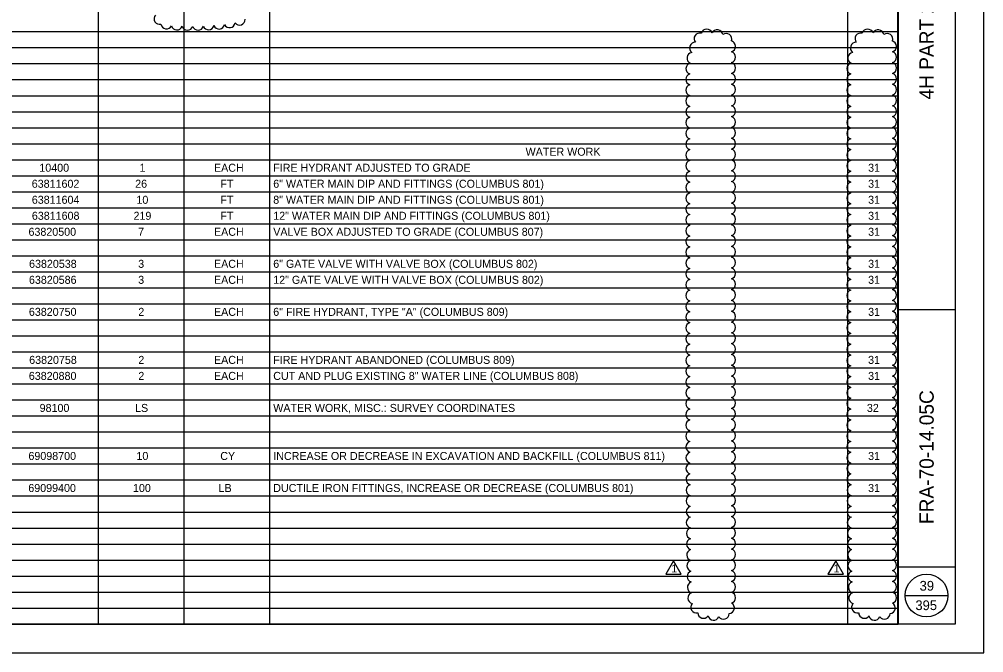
# Model space of a CAD drawing. Extents: x 0 to 34, y 0 to 22.
# Drawn here: x 17.12 to 34, y 0 to 11.08 of the extents above; entities that cross this region are included whole.
import ezdxf

# ---------------------------------------------------------------- set-up
doc = ezdxf.new("R2010")
doc.units = 0
for name, color, linetype in [('SH_Border', 7, 'Continuous'), ('SH_Cut_Line', 7, 'Continuous'), ('SH_Data', 7, 'Continuous'), ('SH_Text', 7, 'Continuous'), ('TX_P_1000', 7, 'Continuous')]:
    doc.layers.add(name, color=color, linetype=linetype)

msp = doc.modelspace()

# ---------------------------------------------------------------- linework, layer by layer
at = {"layer": 'SH_Border'}
for p, q in [((32.5, 0.5), (32.5, 21.5)), ((32.5, 6), (33.5, 6)), ((32.5, 1.5), (33.5, 1.5))]:
    msp.add_line(p, q, dxfattribs=at)
msp.add_lwpolyline([(2, 21.5), (33.5, 21.5), (33.5, 0.5), (2, 0.5)], close=True, dxfattribs=at)
at = {"layer": 'SH_Cut_Line'}
msp.add_lwpolyline([(0, 0), (34, 0), (34, 22), (0, 22)], close=True, dxfattribs=at)
at = {"layer": 'SH_Data'}
for p, q in [((18.504, 21.5), (18.504, 0.5)), ((20.002, 21.5), (20.002, 0.5)), ((21.501, 21.5), (21.501, 0.5)), ((31.614, 21.5), (31.614, 0.5)), ((32.504, 21.5), (32.504, 0.5)), ((2, 10.86), (32.504, 10.86)), ((2, 10.58), (32.504, 10.58)), ((2, 10.3), (32.504, 10.3)), ((2, 10.02), (32.504, 10.02)), ((2, 9.74), (32.504, 9.74)), ((2, 9.46), (32.504, 9.46)), ((2, 9.18), (32.504, 9.18)), ((2, 8.9), (32.504, 8.9)), ((2, 8.62), (32.504, 8.62)), ((2, 8.34), (32.504, 8.34)), ((2, 8.06), (32.504, 8.06)), ((2, 7.78), (32.504, 7.78)), ((2, 7.5), (32.504, 7.5)), ((2, 7.22), (32.504, 7.22)), ((2, 6.94), (32.504, 6.94)), ((2, 6.66), (32.504, 6.66)), ((2, 6.38), (32.504, 6.38)), ((2, 6.1), (32.504, 6.1)), ((2, 5.82), (32.504, 5.82)), ((2, 5.54), (32.504, 5.54)), ((2, 5.26), (32.504, 5.26)), ((2, 4.98), (32.504, 4.98)), ((2, 4.7), (32.504, 4.7)), ((2, 4.42), (32.504, 4.42)), ((2, 4.14), (32.504, 4.14)), ((2, 3.86), (32.504, 3.86)), ((2, 3.58), (32.504, 3.58)), ((2, 3.3), (32.504, 3.3)), ((2, 3.02), (32.504, 3.02)), ((2, 2.74), (32.504, 2.74)), ((2, 2.46), (32.504, 2.46)), ((2, 2.18), (32.504, 2.18)), ((2, 1.9), (32.504, 1.9)), ((2, 1.62), (32.504, 1.62)), ((2, 1.34), (32.504, 1.34)), ((2, 1.06), (32.504, 1.06)), ((32.625, 1), (33.375, 1)), ((2, 0.78), (32.504, 0.78)), ((2, 0.5), (32.504, 0.5))]:
    msp.add_line(p, q, dxfattribs=at)
msp.add_circle((33, 1), 0.375, dxfattribs=at)
at = {"layer": 'TX_P_1000'}
for points in [[(28.571, 1.608), (28.435, 1.372), (28.708, 1.372)], [(31.411, 1.608), (31.274, 1.372), (31.547, 1.372)]]:
    msp.add_lwpolyline(points, close=True, dxfattribs=at)
for centre, radius, start, end in [((19.578, 11.085), 0.0976, 139.2641, 284.2641), ((19.699, 11.005), 0.0976, 188.32, 333.32), ((20.62, 11.003), 0.0976, 202.8824, 347.8824), ((20.803, 11.026), 0.0976, 206.7346, 351.7346), ((20.977, 11.072), 0.0977, 217.3339, 2.3339), ((19.88, 10.986), 0.0976, 195.1082, 340.1082), ((20.065, 10.982), 0.0976, 197.1836, 342.1836), ((20.251, 10.983), 0.0976, 198.6029, 343.6029), ((20.436, 10.99), 0.0976, 200.3873, 345.3873), ((29.031, 10.736), 0.099, 74.4093, 219.4093), ((29.153, 10.805), 0.0991, 19.2496, 164.2496), ((29.336, 10.794), 0.0991, 9.041, 154.041), ((29.491, 10.729), 0.099, 340.6755, 125.6755), ((31.847, 10.736), 0.099, 74.4093, 219.4093), ((31.969, 10.805), 0.0991, 19.2496, 164.2496), ((32.152, 10.794), 0.0991, 9.041, 154.041), ((32.308, 10.729), 0.099, 340.6755, 125.6755), ((28.95, 10.574), 0.0991, 87.314, 232.314), ((29.557, 10.601), 0.0992, 288.6913, 73.6913), ((31.766, 10.574), 0.0991, 87.314, 232.314), ((32.373, 10.601), 0.0992, 288.6913, 73.6913), ((28.906, 10.398), 0.0991, 99.6335, 244.6335), ((29.559, 10.413), 0.0991, 287.5, 72.5), ((31.722, 10.398), 0.0991, 99.6335, 244.6335), ((32.375, 10.413), 0.0991, 287.5, 72.5), ((28.889, 10.213), 0.0991, 105.2456, 250.2456), ((29.559, 10.224), 0.0991, 287.5, 72.5), ((31.706, 10.213), 0.0991, 105.2456, 250.2456), ((32.375, 10.224), 0.0991, 287.5, 72.5), ((29.559, 10.035), 0.0991, 287.5, 72.5), ((32.375, 10.035), 0.0991, 287.5, 72.5), ((28.886, 10.025), 0.0991, 107.4797, 252.4797), ((31.702, 10.025), 0.0991, 107.4797, 252.4797), ((28.885, 9.836), 0.0991, 107.5, 252.5), ((29.559, 9.846), 0.0991, 287.5, 72.5), ((31.702, 9.836), 0.0991, 107.5, 252.5), ((32.375, 9.846), 0.0991, 287.5, 72.5), ((28.885, 9.647), 0.0991, 107.5, 252.5), ((29.559, 9.657), 0.0991, 287.5, 72.5), ((31.702, 9.647), 0.0991, 107.5, 252.5), ((32.375, 9.657), 0.0991, 287.5, 72.5), ((28.885, 9.458), 0.0991, 107.5, 252.5), ((29.559, 9.468), 0.0991, 287.5, 72.5), ((31.702, 9.458), 0.0991, 107.5, 252.5), ((32.375, 9.468), 0.0991, 287.5, 72.5), ((28.885, 9.269), 0.0991, 107.5, 252.5), ((29.559, 9.279), 0.0991, 287.5, 72.5), ((31.702, 9.269), 0.0991, 107.5, 252.5), ((32.375, 9.279), 0.0991, 287.5, 72.5), ((28.885, 9.08), 0.0991, 107.5, 252.5), ((29.559, 9.09), 0.0991, 287.5, 72.5), ((31.702, 9.08), 0.0991, 107.5, 252.5), ((32.375, 9.09), 0.0991, 287.5, 72.5), ((28.885, 8.891), 0.0991, 107.5, 252.5), ((29.559, 8.901), 0.0991, 287.5, 72.5), ((31.702, 8.891), 0.0991, 107.5, 252.5), ((32.375, 8.901), 0.0991, 287.5, 72.5), ((28.885, 8.702), 0.0991, 107.5, 252.5), ((29.559, 8.712), 0.0991, 287.5, 72.5), ((31.702, 8.702), 0.0991, 107.5, 252.5), ((32.375, 8.712), 0.0991, 287.5, 72.5), ((28.885, 8.513), 0.0991, 107.5, 252.5), ((29.559, 8.523), 0.0991, 287.5, 72.5), ((31.702, 8.513), 0.0991, 107.5, 252.5), ((32.375, 8.523), 0.0991, 287.5, 72.5), ((28.885, 8.324), 0.0991, 107.5, 252.5), ((29.559, 8.334), 0.0991, 287.5, 72.5), ((31.702, 8.324), 0.0991, 107.5, 252.5), ((32.375, 8.334), 0.0991, 287.5, 72.5), ((28.885, 8.135), 0.0991, 107.5, 252.5), ((29.559, 8.145), 0.0991, 287.5, 72.5), ((31.702, 8.135), 0.0991, 107.5, 252.5), ((32.375, 8.145), 0.0991, 287.5, 72.5), ((28.885, 7.946), 0.0991, 107.5, 252.5), ((29.559, 7.956), 0.0991, 287.5, 72.5), ((31.702, 7.946), 0.0991, 107.5, 252.5), ((32.375, 7.956), 0.0991, 287.5, 72.5), ((28.885, 7.757), 0.0991, 107.5, 252.5), ((29.559, 7.767), 0.0991, 287.5, 72.5), ((31.702, 7.757), 0.0991, 107.5, 252.5), ((32.375, 7.767), 0.0991, 287.5, 72.5), ((28.885, 7.568), 0.0991, 107.5, 252.5), ((29.559, 7.578), 0.0991, 287.5, 72.5), ((31.702, 7.568), 0.0991, 107.5, 252.5), ((32.375, 7.578), 0.0991, 287.5, 72.5), ((28.885, 7.379), 0.0991, 107.5, 252.5), ((29.559, 7.389), 0.0991, 287.5, 72.5), ((31.702, 7.379), 0.0991, 107.5, 252.5), ((32.375, 7.389), 0.0991, 287.5, 72.5), ((28.885, 7.19), 0.0991, 107.5, 252.5), ((29.559, 7.2), 0.0991, 287.5, 72.5), ((31.702, 7.19), 0.0991, 107.5, 252.5), ((32.375, 7.2), 0.0991, 287.5, 72.5), ((28.885, 7.001), 0.0991, 107.5, 252.5), ((29.559, 7.011), 0.0991, 287.5, 72.5), ((31.702, 7.001), 0.0991, 107.5, 252.5), ((32.375, 7.011), 0.0991, 287.5, 72.5), ((28.885, 6.812), 0.0991, 107.5, 252.5), ((29.559, 6.822), 0.0991, 287.5, 72.5), ((31.702, 6.812), 0.0991, 107.5, 252.5), ((32.375, 6.822), 0.0991, 287.5, 72.5), ((28.885, 6.623), 0.0991, 107.5, 252.5), ((29.559, 6.633), 0.0991, 287.5, 72.5), ((31.702, 6.623), 0.0991, 107.5, 252.5), ((32.375, 6.633), 0.0991, 287.5, 72.5), ((28.885, 6.434), 0.0991, 107.5, 252.5), ((29.559, 6.444), 0.0991, 287.5, 72.5), ((31.702, 6.434), 0.0991, 107.5, 252.5), ((32.375, 6.444), 0.0991, 287.5, 72.5), ((28.885, 6.245), 0.0991, 107.5, 252.5), ((29.559, 6.255), 0.0991, 287.5, 72.5), ((31.702, 6.245), 0.0991, 107.5, 252.5), ((32.375, 6.255), 0.0991, 287.5, 72.5), ((28.885, 6.056), 0.0991, 107.5, 252.5), ((29.559, 6.066), 0.0991, 287.5, 72.5), ((31.702, 6.056), 0.0991, 107.5, 252.5), ((32.375, 6.066), 0.0991, 287.5, 72.5), ((28.885, 5.867), 0.0991, 107.5, 252.5), ((29.559, 5.877), 0.0991, 287.5, 72.5), ((31.702, 5.867), 0.0991, 107.5, 252.5), ((32.375, 5.877), 0.0991, 287.5, 72.5), ((28.885, 5.678), 0.0991, 107.5, 252.5), ((29.559, 5.688), 0.0991, 287.5, 72.5), ((31.702, 5.678), 0.0991, 107.5, 252.5), ((32.375, 5.688), 0.0991, 287.5, 72.5), ((28.885, 5.489), 0.0991, 107.5, 252.5), ((29.559, 5.499), 0.0991, 287.5, 72.5), ((31.702, 5.489), 0.0991, 107.5, 252.5), ((32.375, 5.499), 0.0991, 287.5, 72.5), ((29.559, 5.31), 0.0991, 287.5, 72.5), ((32.375, 5.31), 0.0991, 287.5, 72.5), ((28.885, 5.3), 0.0991, 107.5, 252.5), ((31.702, 5.3), 0.0991, 107.5, 252.5), ((28.886, 5.111), 0.0991, 107.5091, 252.5091), ((29.559, 5.121), 0.0991, 287.5, 72.5), ((31.702, 5.111), 0.0991, 107.5091, 252.5091), ((32.375, 5.121), 0.0991, 287.5, 72.5), ((28.886, 4.922), 0.0991, 107.5258, 252.5258), ((29.559, 4.932), 0.0991, 287.5, 72.5), ((31.702, 4.922), 0.0991, 107.5258, 252.5258), ((32.375, 4.932), 0.0991, 287.5, 72.5), ((28.886, 4.733), 0.0991, 107.5437, 252.5437), ((29.559, 4.743), 0.0991, 287.5, 72.5), ((31.702, 4.733), 0.0991, 107.5437, 252.5437), ((32.375, 4.743), 0.0991, 287.5, 72.5), ((28.886, 4.544), 0.0991, 107.5629, 252.5629), ((29.559, 4.554), 0.0991, 287.5, 72.5), ((31.702, 4.544), 0.0991, 107.5629, 252.5629), ((32.375, 4.554), 0.0991, 287.5, 72.5), ((28.886, 4.355), 0.0991, 107.5836, 252.5836), ((29.559, 4.365), 0.0991, 287.5, 72.5), ((31.703, 4.355), 0.0991, 107.5836, 252.5836), ((32.375, 4.365), 0.0991, 287.5, 72.5), ((28.886, 4.166), 0.0991, 107.606, 252.606), ((29.559, 4.176), 0.0991, 287.5, 72.5), ((31.703, 4.166), 0.0991, 107.606, 252.606), ((32.375, 4.176), 0.0991, 287.5, 72.5), ((28.887, 3.977), 0.0991, 107.6303, 252.6303), ((29.559, 3.987), 0.0991, 287.5, 72.5), ((31.703, 3.977), 0.0991, 107.6303, 252.6303), ((32.375, 3.987), 0.0991, 287.5, 72.5), ((28.887, 3.788), 0.0991, 107.6568, 252.6568), ((29.559, 3.797), 0.0991, 287.5, 72.5), ((31.704, 3.788), 0.0991, 107.6568, 252.6568), ((32.375, 3.797), 0.0991, 287.5, 72.5), ((28.888, 3.599), 0.0991, 107.6859, 252.6859), ((29.559, 3.608), 0.0991, 287.5, 72.5), ((31.704, 3.599), 0.0991, 107.6859, 252.6859), ((32.375, 3.608), 0.0991, 287.5, 72.5), ((28.889, 3.41), 0.0991, 107.718, 252.718), ((29.559, 3.419), 0.0991, 287.5, 72.5), ((31.705, 3.41), 0.0991, 107.718, 252.718), ((32.375, 3.419), 0.0991, 287.5, 72.5), ((28.889, 3.221), 0.0991, 107.7537, 252.7537), ((29.559, 3.23), 0.0991, 287.5, 72.5), ((31.706, 3.221), 0.0991, 107.7537, 252.7537), ((32.375, 3.23), 0.0991, 287.5, 72.5), ((28.89, 3.032), 0.0991, 107.7938, 252.7938), ((29.559, 3.041), 0.0991, 287.5, 72.5), ((31.707, 3.032), 0.0991, 107.7938, 252.7938), ((32.375, 3.041), 0.0991, 287.5, 72.5), ((28.891, 2.843), 0.0991, 107.8391, 252.8391), ((29.559, 2.852), 0.0991, 287.5, 72.5), ((31.708, 2.843), 0.0991, 107.8391, 252.8391), ((32.375, 2.852), 0.0991, 287.5, 72.5), ((28.892, 2.654), 0.0991, 107.8909, 252.8909), ((29.559, 2.663), 0.0991, 287.5, 72.5), ((31.709, 2.654), 0.0991, 107.8909, 252.8909), ((32.375, 2.663), 0.0991, 287.5, 72.5), ((28.894, 2.465), 0.0991, 107.951, 252.951), ((29.559, 2.474), 0.0991, 287.5, 72.5), ((31.71, 2.465), 0.0991, 107.951, 252.951), ((32.375, 2.474), 0.0991, 287.5, 72.5), ((28.895, 2.276), 0.0991, 108.0219, 253.0219), ((29.559, 2.285), 0.0991, 287.5, 72.5), ((31.712, 2.276), 0.0991, 108.0219, 253.0219), ((32.375, 2.285), 0.0991, 287.5, 72.5), ((28.897, 2.087), 0.0991, 108.1071, 253.1071), ((29.559, 2.096), 0.0991, 287.5, 72.5), ((31.714, 2.087), 0.0991, 108.1071, 253.1071), ((32.375, 2.096), 0.0991, 287.5, 72.5), ((28.899, 1.898), 0.0991, 108.2123, 253.2123), ((29.559, 1.907), 0.0991, 287.5, 72.5), ((31.716, 1.898), 0.0991, 108.2123, 253.2123), ((32.375, 1.907), 0.0991, 287.5, 72.5), ((28.902, 1.709), 0.0991, 108.3469, 253.3469), ((29.559, 1.718), 0.0991, 287.5, 72.5), ((31.719, 1.709), 0.0991, 108.3469, 253.3469), ((32.375, 1.718), 0.0991, 287.5, 72.5), ((28.905, 1.521), 0.0991, 108.5276, 253.5276), ((29.559, 1.529), 0.0991, 287.5, 72.5), ((31.722, 1.521), 0.0991, 108.5276, 253.5276), ((32.375, 1.529), 0.0991, 287.5, 72.5), ((28.909, 1.332), 0.0991, 108.7891, 253.7891), ((29.559, 1.34), 0.0991, 287.5, 72.5), ((31.725, 1.332), 0.0991, 108.7891, 253.7891), ((32.375, 1.34), 0.0991, 287.5, 72.5), ((28.914, 1.143), 0.0991, 109.2189, 254.2189), ((29.559, 1.151), 0.0991, 287.5, 72.5), ((31.73, 1.143), 0.0991, 109.2189, 254.2189), ((32.375, 1.151), 0.0991, 287.5, 72.5), ((28.921, 0.955), 0.0991, 110.1571, 255.1571), ((29.559, 0.962), 0.0991, 287.5, 72.5), ((31.738, 0.955), 0.0991, 110.1571, 255.1571), ((32.375, 0.962), 0.0991, 287.5, 72.5), ((28.971, 0.794), 0.0991, 139.2663, 284.2663), ((29.538, 0.783), 0.0991, 274.2898, 59.2898), ((31.787, 0.794), 0.0991, 139.2663, 284.2663), ((32.354, 0.783), 0.0991, 274.2898, 59.2898), ((29.094, 0.7), 0.0991, 180.783, 325.783), ((29.446, 0.685), 0.0991, 214.5703, 359.5703), ((31.911, 0.7), 0.0991, 180.783, 325.783), ((32.263, 0.685), 0.0991, 214.5703, 359.5703), ((29.273, 0.666), 0.0991, 192.8167, 337.8167), ((32.089, 0.666), 0.0991, 192.8167, 337.8167)]:
    msp.add_arc(centre, radius, start, end, dxfattribs=at)

# ---------------------------------------------------------------- texts
at = {"layer": 'SH_Data'}
for s, p in [('4H PART 2 GENERAL SUMMARY', (33.125, 9.672)), ('FRA-70-14.05C', (33.125, 2.249))]:
    msp.add_text(s, height=0.25, rotation=90, dxfattribs=at).set_placement(p)
at = {"layer": 'SH_Text'}
for s, height, p in [('WATER WORK', 0.14, (25.983, 8.69)), ('10400', 0.14, (17.474, 8.41)), ('1', 0.14, (19.227, 8.41)), ('EACH', 0.14, (20.53, 8.41)), ('FIRE HYDRANT ADJUSTED TO GRADE', 0.14, (21.567, 8.41)), ('31', 0.14, (31.977, 8.41)), ('63811602', 0.14, (17.341, 8.13)), ('26', 0.14, (19.151, 8.13)), ('FT', 0.14, (20.642, 8.13)), ('6" WATER MAIN DIP AND FITTINGS (COLUMBUS 801)', 0.14, (21.567, 8.13)), ('31', 0.14, (31.977, 8.13)), ('63811604', 0.14, (17.342, 7.85)), ('10', 0.14, (19.173, 7.85)), ('FT', 0.14, (20.642, 7.85)), ('8" WATER MAIN DIP AND FITTINGS (COLUMBUS 801)', 0.14, (21.567, 7.85)), ('31', 0.14, (31.977, 7.85)), ('63811608', 0.14, (17.343, 7.57)), ('219', 0.14, (19.122, 7.57)), ('FT', 0.14, (20.642, 7.57)), ('12" WATER MAIN DIP AND FITTINGS (COLUMBUS 801)', 0.14, (21.567, 7.57)), ('31', 0.14, (31.977, 7.57)), ('63820500', 0.14, (17.284, 7.29)), ('7', 0.14, (19.202, 7.29)), ('EACH', 0.14, (20.53, 7.29)), ('VALVE BOX ADJUSTED TO GRADE (COLUMBUS 807)', 0.14, (21.567, 7.29)), ('31', 0.14, (31.977, 7.29)), ('63820538', 0.14, (17.294, 6.73)), ('3', 0.14, (19.204, 6.73)), ('EACH', 0.14, (20.53, 6.73)), ('6" GATE VALVE WITH VALVE BOX (COLUMBUS 802)', 0.14, (21.567, 6.73)), ('31', 0.14, (31.977, 6.73)), ('63820586', 0.14, (17.292, 6.45)), ('3', 0.14, (19.204, 6.45)), ('EACH', 0.14, (20.53, 6.45)), ('12" GATE VALVE WITH VALVE BOX (COLUMBUS 802)', 0.14, (21.567, 6.45)), ('31', 0.14, (31.977, 6.45)), ('63820750', 0.14, (17.291, 5.89)), ('2', 0.14, (19.206, 5.89)), ('EACH', 0.14, (20.53, 5.89)), ('6" FIRE HYDRANT, TYPE "A" (COLUMBUS 809)', 0.14, (21.567, 5.89)), ('31', 0.14, (31.977, 5.89)), ('63820758', 0.14, (17.296, 5.05)), ('2', 0.14, (19.206, 5.05)), ('EACH', 0.14, (20.53, 5.05)), ('FIRE HYDRANT ABANDONED (COLUMBUS 809)', 0.14, (21.567, 5.05)), ('31', 0.14, (31.977, 5.05)), ('63820880', 0.14, (17.29, 4.77)), ('2', 0.14, (19.206, 4.77)), ('EACH', 0.14, (20.53, 4.77)), ('CUT AND PLUG EXISTING 8" WATER LINE (COLUMBUS 808)', 0.14, (21.567, 4.77)), ('31', 0.14, (31.977, 4.77)), ('98100', 0.14, (17.479, 4.21)), ('LS', 0.14, (19.149, 4.21)), ('WATER WORK, MISC.: SURVEY COORDINATES', 0.14, (21.567, 4.21)), ('32', 0.14, (31.956, 4.21)), ('69098700', 0.14, (17.283, 3.37)), ('10', 0.14, (19.173, 3.37)), ('CY', 0.14, (20.64, 3.37)), ('INCREASE OR DECREASE IN EXCAVATION AND BACKFILL (COLUMBUS 811)', 0.14, (21.567, 3.37)), ('31', 0.14, (31.977, 3.37)), ('69099400', 0.14, (17.281, 2.81)), ('100', 0.14, (19.113, 2.81)), ('LB ', 0.14, (20.61, 2.81)), ('DUCTILE IRON FITTINGS, INCREASE OR DECREASE (COLUMBUS 801)', 0.14, (21.567, 2.81)), ('31', 0.14, (31.977, 2.81)), ('39', 0.17, (32.878, 1.085)), ('395', 0.17, (32.804, 0.745))]:
    msp.add_text(s, height=height, dxfattribs=at).set_placement(p)
at = {"layer": 'TX_P_1000'}
for p in [(28.532, 1.403), (31.372, 1.403)]:
    msp.add_text('1', height=0.14, rotation=360, dxfattribs=at).set_placement(p)

doc.saveas('drawing.dxf')
